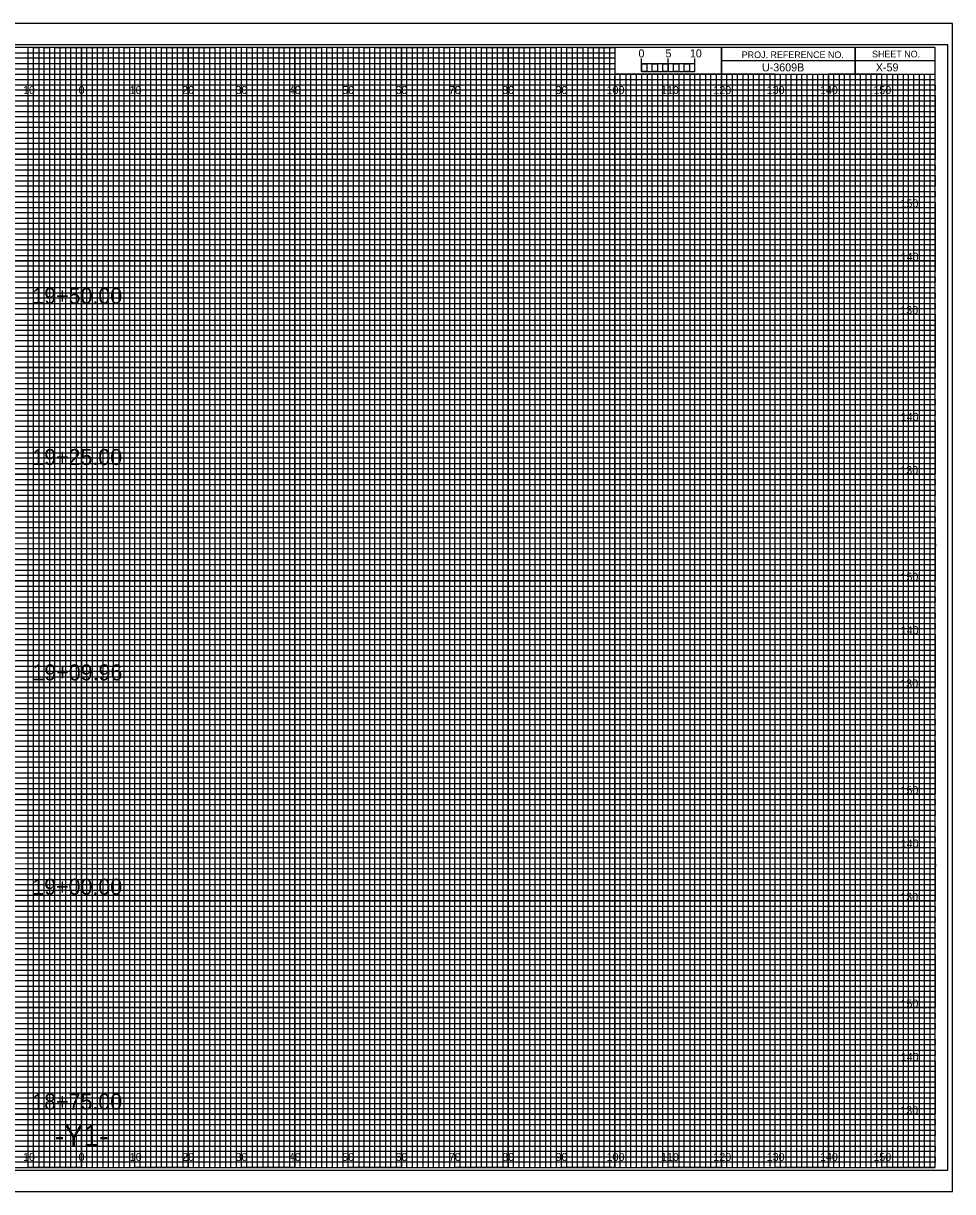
# Model space of a CAD drawing. Extents: x -13 to 323, y -5 to 2634.
# Drawn here: x 149.1 to 323.3, y 1535.5 to 1754.5 of the extents above; entities that cross this region are included whole.
import ezdxf

# ---------------------------------------------------------------- set-up
doc = ezdxf.new("R2010")
doc.units = 0
for name, color, linetype in [('Exist Cross Section Cell', 7, 'Continuous'), ('Exist XS Center Line Elevation Label', 7, 'Continuous'), ('Exist XS Ground Line', 7, 'Continuous'), ('Prop CMT Pvmt Course 1', 7, 'Continuous'), ('Prop CMT Pvmt Course 1 Wedge', 7, 'Continuous'), ('Prop CMT Pvmt Course 2', 7, 'Continuous'), ('Prop CMT Pvmt Course 2 Wedge', 7, 'Continuous'), ('Prop CMT Pvmt Course 3', 7, 'Continuous'), ('Prop CMT Pvmt Course 3 Wedge', 7, 'Continuous'), ('Prop CMT Pvmt Surface Shoulder', 7, 'Continuous'), ('Prop CMT Pvmt Wedge Surface 3', 7, 'Continuous'), ('Prop CMT Shld Paved Course 1', 7, 'Continuous'), ('Prop CMT Shld Paved Course 2', 7, 'Continuous'), ('Prop CMT Shld Paved Course 3', 7, 'Continuous'), ('Prop CMT Slope Grass', 7, 'Continuous'), ('Prop CMT Subgrade Earthwork', 7, 'Continuous'), ('Scratch_Level_0', 7, 'Continuous')]:
    doc.layers.add(name, color=color, linetype=linetype)

msp = doc.modelspace()

# ---------------------------------------------------------------- linework, layer by layer
at = {"layer": 'Exist XS Center Line Elevation Label'}
for points in [[(145, 1540), (155, 1540), (155, 1750), (165, 1750), (165, 1540), (175, 1540), (175, 1750), (185, 1750), (185, 1540), (195, 1540), (195, 1750), (205, 1750), (205, 1540), (215, 1540), (215, 1750), (225, 1750), (225, 1540), (235, 1540), (235, 1750), (245, 1750), (245, 1540), (255, 1540), (255, 1750), (259.93, 1750), (260, 1750), (260, 1745), (264.99, 1745), (264.99, 1540), (275, 1540), (275, 1745), (285, 1745), (285, 1540), (295, 1540), (295, 1745), (305, 1745), (305, 1540), (315, 1540), (315, 1745)], [(0, 1745), (275, 1745)], [(0, 1725), (320, 1725), (320, 1735), (0, 1735)], [(0, 1705), (320, 1705), (320, 1715), (0, 1715)], [(0, 1685), (320, 1685), (320, 1695), (0, 1695)], [(0, 1665), (320, 1665), (320, 1675), (0, 1675)], [(0, 1645), (320, 1645), (320, 1655), (0, 1655)], [(0, 1625), (320, 1625), (320, 1635), (0, 1635)], [(0, 1605), (320, 1605), (320, 1615), (0, 1615)], [(0, 1585), (320, 1585), (320, 1595), (0, 1595)], [(0, 1565), (320, 1565), (320, 1575), (0, 1575)], [(0, 1545), (320, 1545), (320, 1555), (0, 1555)]]:
    msp.add_lwpolyline(points, dxfattribs=at)
at = {"layer": 'Exist XS Ground Line'}
for p, q in [((150, 1750), (140, 1750)), ((150, 1540), (150, 1750)), ((170, 1750), (160, 1750)), ((160, 1750), (160, 1540)), ((170, 1540), (170, 1750)), ((190, 1750), (180, 1750)), ((180, 1750), (180, 1540)), ((190, 1540), (190, 1750)), ((210, 1750), (200, 1750)), ((200, 1750), (200, 1540)), ((210, 1540), (210, 1750)), ((230, 1750), (220, 1750)), ((220, 1750), (220, 1540)), ((230, 1540), (230, 1750)), ((250, 1750), (240, 1750)), ((240, 1750), (240, 1540)), ((250, 1540), (250, 1750)), ((260, 1750), (260, 1540)), ((270, 1540), (270, 1745)), ((290, 1745), (280, 1745)), ((280, 1745), (280, 1540)), ((290, 1540), (290, 1745)), ((310, 1745), (300, 1745)), ((300, 1745), (300, 1540)), ((310, 1540), (310, 1745)), ((160, 1540), (150, 1540)), ((180, 1540), (170, 1540)), ((200, 1540), (190, 1540)), ((220, 1540), (210, 1540)), ((240, 1540), (230, 1540)), ((260, 1540), (250, 1540)), ((280, 1540), (270, 1540)), ((300, 1540), (290, 1540)), ((320, 1540), (310, 1540)), ((320, 1540), (320, 1540))]:
    msp.add_line(p, q, dxfattribs=at)
for points in [[(0, 1740), (320, 1740), (320, 1730), (0, 1730)], [(0, 1720), (320, 1720), (320, 1710), (0, 1710)], [(0, 1700), (320, 1700), (320, 1690), (0, 1690)], [(0, 1680), (320, 1680), (320, 1670), (0, 1670)], [(0, 1660), (320, 1660), (320, 1650), (0, 1650)], [(0, 1640), (320, 1640), (320, 1630), (0, 1630)], [(0, 1620), (320, 1620), (320, 1610), (0, 1610)], [(0, 1600), (320, 1600), (320, 1590), (0, 1590)], [(0, 1580), (320, 1580), (320, 1570), (0, 1570)], [(0, 1560), (320, 1560), (320, 1550), (0, 1550)]]:
    msp.add_lwpolyline(points, dxfattribs=at)
at = {"layer": 'Prop CMT Pvmt Course 1'}
for p, q in [((265, 1745.49), (265, 1747.9)), ((265, 1746.9), (265, 1747.9)), ((270, 1745.49), (270, 1747.9)), ((275, 1745.49), (275, 1747.9)), ((275, 1746.9), (275, 1747.9))]:
    msp.add_line(p, q, dxfattribs=at)
for points in [[(275, 1746.9), (265, 1746.9), (265, 1745.49), (275, 1745.49)], [(265, 1746.9), (266, 1746.9), (266, 1745.49), (265, 1745.49)], [(267, 1746.9), (268, 1746.9), (268, 1745.49), (267, 1745.49)], [(269, 1746.9), (270, 1746.9), (270, 1745.49), (269, 1745.49)], [(271, 1746.9), (272, 1746.9), (272, 1745.49), (271, 1745.49)], [(273, 1746.9), (274, 1746.9), (274, 1745.49), (273, 1745.49)]]:
    msp.add_lwpolyline(points, close=True, dxfattribs=at)
at = {"layer": 'Prop CMT Pvmt Surface Shoulder'}
for p, q in [((267, 1745), (266.01, 1745)), ((266.01, 1745), (266.01, 1540)), ((267, 1540), (267, 1745)), ((269, 1745), (268, 1745)), ((268, 1745), (268, 1540)), ((269, 1540), (269, 1745)), ((266.01, 1540), (265, 1540)), ((268, 1540), (267, 1540))]:
    msp.add_line(p, q, dxfattribs=at)
for points in [[(150, 1540), (151, 1540), (151, 1750), (152, 1750), (152, 1540)], [(152, 1540), (153, 1540), (153, 1750), (154, 1750), (154, 1540)], [(155, 1540), (156, 1540), (156, 1750), (157, 1750), (157, 1540)], [(157, 1540), (158, 1540), (158, 1750), (159, 1750), (159, 1540)], [(160, 1540), (161, 1540), (161, 1750), (162, 1750), (162, 1540)], [(162, 1540), (163, 1540), (163, 1750), (164, 1750), (164, 1540)], [(165, 1540), (166, 1540), (166, 1750), (167, 1750), (167, 1540)], [(167, 1540), (168, 1540), (168, 1750), (169, 1750), (169, 1540)], [(170, 1540), (171, 1540), (171, 1750), (172, 1750), (172, 1540)], [(172, 1540), (173, 1540), (173, 1750), (174, 1750), (174, 1540)], [(175, 1540), (176, 1540), (176, 1750), (177, 1750), (177, 1540)], [(177, 1540), (178, 1540), (178, 1750), (179, 1750), (179, 1540)], [(180, 1540), (181, 1540), (181, 1750), (182, 1750), (182, 1540)], [(182, 1540), (183, 1540), (183, 1750), (184, 1750), (184, 1540)], [(185, 1540), (186, 1540), (186, 1750), (187, 1750), (187, 1540)], [(187, 1540), (188, 1540), (188, 1750), (189, 1750), (189, 1540)], [(190, 1540), (191, 1540), (191, 1750), (192, 1750), (192, 1540)], [(192, 1540), (193, 1540), (193, 1750), (194, 1750), (194, 1540)], [(195, 1540), (196, 1540), (196, 1750), (197, 1750), (197, 1540)], [(197, 1540), (198, 1540), (198, 1750), (199, 1750), (199, 1540)], [(200, 1540), (201, 1540), (201, 1750), (202, 1750), (202, 1540)], [(202, 1540), (203, 1540), (203, 1750), (204, 1750), (204, 1540)], [(205, 1540), (206, 1540), (206, 1750), (207, 1750), (207, 1540)], [(207, 1540), (208, 1540), (208, 1750), (209, 1750), (209, 1540)], [(210, 1540), (211, 1540), (211, 1750), (212, 1750), (212, 1540)], [(212, 1540), (213, 1540), (213, 1750), (214, 1750), (214, 1540)], [(215, 1540), (216, 1540), (216, 1750), (217, 1750), (217, 1540)], [(217, 1540), (218, 1540), (218, 1750), (219, 1750), (219, 1540)], [(220, 1540), (221, 1540), (221, 1750), (222, 1750), (222, 1540)], [(222, 1540), (223, 1540), (223, 1750), (224, 1750), (224, 1540)], [(225, 1540), (226, 1540), (226, 1750), (227, 1750), (227, 1540)], [(227, 1540), (228, 1540), (228, 1750), (229, 1750), (229, 1540)], [(230, 1540), (231, 1540), (231, 1750), (232, 1750), (232, 1540)], [(232, 1540), (233, 1540), (233, 1750), (234, 1750), (234, 1540)], [(235, 1540), (236, 1540), (236, 1750), (237, 1750), (237, 1540)], [(237, 1540), (238, 1540), (238, 1750), (239, 1750), (239, 1540)], [(240, 1540), (241, 1540), (241, 1750), (242, 1750), (242, 1540)], [(242, 1540), (243, 1540), (243, 1750), (244, 1750), (244, 1540)], [(245, 1540), (246, 1540), (246, 1750), (247, 1750), (247, 1540)], [(247, 1540), (248, 1540), (248, 1750), (249, 1750), (249, 1540)], [(250, 1540), (251, 1540), (251, 1750), (252, 1750), (252, 1540)], [(252, 1540), (253, 1540), (253, 1750), (254, 1750), (254, 1540)], [(255, 1540), (256, 1540), (256, 1750), (257, 1750), (257, 1540)], [(257, 1540), (258, 1540), (258, 1750), (259, 1750), (259, 1540)], [(260, 1540), (261, 1540), (261, 1745), (262.02, 1745), (262.02, 1540)], [(262, 1540), (263, 1540), (263, 1745), (263.99, 1745), (263.99, 1540)], [(270, 1540), (270.98, 1540), (270.98, 1745), (272, 1745), (272, 1540)], [(272, 1540), (273, 1540), (273, 1745), (274.05, 1745), (274.05, 1540)], [(275, 1540), (276, 1540), (276, 1745), (277, 1745), (277, 1540)], [(277, 1540), (278, 1540), (278, 1745), (279, 1745), (279, 1540)], [(280, 1540), (281, 1540), (281, 1745), (282, 1745), (282, 1540)], [(282, 1540), (283, 1540), (283, 1745), (284, 1745), (284, 1540)], [(285, 1540), (286, 1540), (286, 1745), (287, 1745), (287, 1540)], [(287, 1540), (288, 1540), (288, 1745), (289, 1745), (289, 1540)], [(290, 1540), (291, 1540), (291, 1745), (292, 1745), (292, 1540)], [(292, 1540), (293, 1540), (293, 1745), (294, 1745), (294, 1540)], [(295, 1540), (296, 1540), (296, 1745), (297, 1745), (297, 1540)], [(297, 1540), (298, 1540), (298, 1745), (299, 1745), (299, 1540)], [(300, 1540), (301, 1540), (301, 1745), (302, 1745), (302, 1540)], [(302, 1540), (303, 1540), (303, 1745), (304, 1745), (304, 1540)], [(305, 1540), (306, 1540), (306, 1745), (307, 1745), (307, 1540)], [(307, 1540), (308, 1540), (308, 1745), (309, 1745), (309, 1540)], [(310, 1540), (311, 1540), (311, 1745), (312, 1745), (312, 1540)], [(312, 1540), (313, 1540), (313, 1745), (314, 1745), (314, 1540)], [(315, 1540), (316, 1540), (316, 1745), (317, 1745), (317, 1540)], [(317, 1540), (318, 1540), (318, 1745), (319, 1745), (319, 1540)]]:
    msp.add_lwpolyline(points, dxfattribs=at)
at = {"layer": 'Prop CMT Pvmt Wedge Surface 3'}
for p, q in [((305, 1750), (305, 1745)), ((305, 1745), (305, 1750)), ((280, 1747.5), (280, 1745)), ((320, 1747.49), (280, 1747.49)), ((280, 1745), (320, 1745))]:
    msp.add_line(p, q, dxfattribs=at)
for points in [[(320, 1750), (0, 1750), (0, 1540), (320, 1540)], [(280, 1750), (260, 1750), (260, 1745.03), (280, 1745.03)], [(320, 1750), (280, 1750), (280, 1745), (320, 1745)]]:
    msp.add_lwpolyline(points, close=True, dxfattribs=at)
at = {"layer": 'Prop CMT Shld Paved Course 1'}
for p, q in [((150, 1540), (150, 1750)), ((160, 1540), (160, 1750)), ((170, 1540), (170, 1750)), ((180, 1540), (180, 1750)), ((190, 1540), (190, 1750)), ((200, 1540), (200, 1750)), ((210, 1540), (210, 1750)), ((220, 1540), (220, 1750)), ((230, 1540), (230, 1750)), ((240, 1540), (240, 1750)), ((250, 1540), (250, 1750)), ((260, 1540), (260, 1744.69)), ((270, 1540), (270, 1744.69)), ((280, 1540), (280, 1744.69)), ((290, 1540), (290, 1744.69)), ((300, 1540), (300, 1744.69)), ((310, 1540), (310, 1744.69)), ((0, 1740), (320, 1740)), ((0, 1730), (320, 1730)), ((0, 1720), (320, 1720)), ((0, 1710), (320, 1710)), ((0, 1700), (320, 1700)), ((0, 1690), (320, 1690)), ((0, 1680), (320, 1680)), ((0, 1670), (320, 1670)), ((0, 1660), (320, 1660)), ((0, 1650), (320, 1650)), ((0, 1640), (320, 1640)), ((0, 1630), (320, 1630)), ((0, 1620), (320, 1620)), ((0, 1610), (320, 1610)), ((0, 1600), (320, 1600)), ((0, 1590), (320, 1590)), ((0, 1580), (320, 1580)), ((0, 1570), (320, 1570)), ((0, 1560), (320, 1560)), ((0, 1550), (320, 1550))]:
    msp.add_line(p, q, dxfattribs=at)
at = {"layer": 'Prop CMT Shld Paved Course 2'}
for p, q in [((323.3, 1754.5), (-13.4, 1754.5)), ((-13.4, 1535.5), (323.3, 1535.5))]:
    msp.add_line(p, q, dxfattribs=at)
at = {"layer": 'Prop CMT Slope Grass'}
msp.add_lwpolyline([(-10.8, 1539.5), (322.4, 1539.5), (322.4, 1750.5), (-10.8, 1750.5)], close=True, dxfattribs=at)
at = {"layer": 'Prop CMT Subgrade Earthwork'}
msp.add_lwpolyline([(-13.4, 1535.5), (323.3, 1535.5), (323.3, 1754.5), (-13.4, 1754.5)], close=True, dxfattribs=at)
at = {"layer": 'Scratch_Level_0'}
for p, q in [((0, 1749), (260, 1749)), ((260, 1747.98), (0, 1747.98)), ((260, 1749), (260, 1747.98)), ((0, 1747), (260, 1747)), ((260, 1745.89), (0, 1745.89)), ((260, 1747), (260, 1745.89)), ((0, 1744), (320, 1744))]:
    msp.add_line(p, q, dxfattribs=at)
for points in [[(0, 1743), (270, 1743), (320, 1743), (320, 1742), (0, 1742)], [(0, 1741), (320, 1741), (320, 1739), (0, 1739)], [(0, 1738), (320, 1738), (320, 1737), (0, 1736.98)], [(0, 1736), (320, 1736), (320, 1734), (0, 1734)], [(0, 1733), (320, 1733), (320, 1732), (0, 1732)], [(0, 1731), (320, 1731), (320, 1729), (0, 1729)], [(0, 1728), (320, 1728), (320, 1727), (0, 1727)], [(0, 1726), (320, 1726), (320, 1724), (0, 1724)], [(0, 1723), (320, 1723), (320, 1722), (0, 1722)], [(0, 1721), (320, 1721), (320, 1719), (0, 1719)], [(0, 1718), (320, 1718), (320, 1717), (0, 1717)], [(0, 1716), (320, 1716), (320, 1713.95), (320, 1713), (320, 1712), (0, 1712)], [(0, 1714), (320, 1714), (320, 1713), (0, 1713)], [(0, 1711), (320, 1711), (320, 1709), (0, 1709.03)], [(0, 1709.03), (320, 1709), (320, 1708), (0, 1708)], [(0, 1707), (320, 1707), (320, 1706), (0, 1706)], [(0, 1704), (320, 1704), (320, 1703), (0, 1703)], [(0, 1702), (320, 1702), (320, 1701), (0, 1701)], [(-0.07, 1698.89), (320, 1698.89), (320, 1697.88), (-0.07, 1697.88)], [(0, 1697), (320, 1697), (320, 1696), (0, 1696)], [(0, 1694), (320, 1694), (320, 1693), (0, 1693)], [(0, 1692), (320, 1692), (320, 1691), (0, 1691)], [(0, 1689), (320, 1689), (320, 1688), (0, 1688)], [(0, 1687), (320, 1687), (320, 1686), (0, 1686)], [(0, 1684), (320, 1684), (320, 1683), (0, 1683)], [(0, 1682), (320, 1682), (320, 1681), (0, 1681)], [(0, 1679), (320, 1679), (319.99, 1677.98), (0, 1678)], [(0, 1677), (320, 1677), (320, 1676), (0, 1676)], [(0, 1674), (320, 1674), (320, 1673), (0, 1673)], [(0, 1672), (320, 1672), (320, 1671), (0, 1671)], [(0, 1669), (320, 1669), (320, 1668), (0, 1668)], [(0, 1667), (320, 1667), (320, 1666), (0, 1666)], [(0, 1664), (320, 1664), (320, 1663), (0, 1663)], [(0, 1662), (320, 1662), (320, 1661), (0, 1661)], [(0, 1659), (320, 1659), (320, 1658), (0, 1658)], [(0, 1656.99), (320.07, 1656.91), (320, 1656), (0, 1656)], [(0, 1654), (320, 1654), (320, 1653), (0, 1653)], [(0, 1652), (320, 1652), (320, 1651), (0, 1651)], [(0, 1649), (320, 1649), (320, 1648), (0, 1648)], [(0, 1647), (320, 1647), (320, 1646), (0, 1646)], [(0, 1644), (320, 1644), (320, 1643), (0, 1643)], [(0, 1642), (320, 1642), (320, 1641), (0, 1641)], [(0, 1639), (320, 1639), (320, 1638), (0, 1638)], [(0, 1637), (320, 1637), (320, 1636), (0, 1636)], [(0, 1634), (320, 1634), (320, 1633), (0, 1633)], [(0, 1632), (320, 1632), (320, 1631), (0, 1631)], [(0, 1629), (320, 1629), (320, 1628), (0, 1628)], [(0, 1627), (320, 1627), (320, 1626), (0, 1626)], [(0, 1624), (320, 1624), (320, 1623), (0, 1623)], [(0, 1622), (320, 1622), (320, 1621), (0, 1621)], [(0, 1619), (320, 1619), (319.99, 1617.98), (0, 1618)], [(0, 1617), (320, 1617), (320, 1616), (0, 1616)], [(0, 1614), (320, 1614), (320, 1613), (0, 1613)], [(0, 1612), (320, 1612), (320, 1611), (0, 1611)], [(0, 1609), (320, 1609), (320, 1608), (0, 1608)], [(0, 1607), (320, 1607), (320, 1606), (0, 1606)], [(0, 1604), (320, 1604), (320, 1603), (0, 1603)], [(0, 1602), (320, 1602), (320, 1601), (0, 1601)], [(0, 1599), (320, 1599), (320, 1598), (0, 1598)], [(0, 1596.99), (320.07, 1596.91), (320, 1596), (0, 1596)], [(0, 1594), (320, 1594), (320, 1593), (0, 1593)], [(0, 1592), (320, 1592), (320, 1591), (0, 1591)], [(0, 1589), (320, 1589), (320, 1588), (0, 1588)], [(0, 1587), (320, 1587), (320, 1586), (0, 1586)], [(0, 1584), (320, 1584), (320, 1583), (0, 1583)], [(0, 1582), (320, 1582), (320, 1581), (0, 1581)], [(0, 1579), (320, 1579), (320, 1578), (0, 1578)], [(0, 1577), (320, 1577), (320, 1576), (0, 1576)], [(0, 1574), (320, 1574), (320, 1573), (0, 1573)], [(0, 1572), (320, 1572), (320, 1571), (0, 1571)], [(0, 1569), (320, 1569), (320, 1568), (0, 1568)], [(0, 1567), (320, 1567), (320, 1566), (0, 1566)], [(0, 1564), (320, 1564), (320, 1563), (0, 1563)], [(0, 1562), (320, 1562), (320, 1561), (0, 1561)], [(0, 1559), (320, 1559), (320, 1558), (0, 1558)], [(0, 1557), (320, 1557), (320, 1556), (0, 1556)], [(0, 1554), (320, 1554), (320, 1553), (0, 1553)], [(0, 1552), (320, 1552), (320, 1551), (0, 1551)], [(0, 1549), (320, 1549), (320, 1548), (0, 1548)], [(0, 1547), (320, 1547), (320, 1546), (0, 1546)], [(0, 1544), (320, 1544), (320, 1543), (0, 1543)], [(0, 1542), (320, 1542), (320, 1541), (0, 1541)]]:
    msp.add_lwpolyline(points, dxfattribs=at)

# ---------------------------------------------------------------- texts
at = {"layer": 'Exist Cross Section Cell'}
for s, p in [('10', (149.04, 1741.25)), ('0', (159.45, 1741.25)), ('0', (159.45, 1741.25)), ('10', (169.04, 1741.25)), ('20', (178.86, 1741.25)), ('30', (188.86, 1741.25)), ('40', (198.86, 1741.25)), ('50', (208.86, 1741.25)), ('60', (218.86, 1741.25)), ('70', (228.86, 1741.25)), ('80', (238.86, 1741.25)), ('90', (248.86, 1741.25)), ('100', (258.44, 1741.25)), ('110', (268.62, 1741.25)), ('120', (278.44, 1741.25)), ('130', (288.44, 1741.25)), ('140', (298.44, 1741.25)), ('150', (308.44, 1741.25)), ('10', (149.04, 1541.25)), ('0', (159.45, 1541.25)), ('0', (159.45, 1541.25)), ('10', (169.04, 1541.25)), ('20', (178.86, 1541.25)), ('30', (188.86, 1541.25)), ('40', (198.86, 1541.25)), ('50', (208.86, 1541.25)), ('60', (218.86, 1541.25)), ('70', (228.86, 1541.25)), ('80', (238.86, 1541.25)), ('90', (248.86, 1541.25)), ('100', (258.44, 1541.25)), ('110', (268.62, 1541.25)), ('120', (278.44, 1541.25)), ('130', (288.44, 1541.25)), ('140', (298.44, 1541.25)), ('150', (308.44, 1541.25))]:
    msp.add_text(s, height=1.5, dxfattribs=at).set_placement(p)
at = {"layer": 'Prop CMT Pvmt Course 1'}
msp.add_text('0', height=1.5, dxfattribs=at).set_placement((264.41, 1748.12))
at = {"layer": 'Prop CMT Pvmt Course 1 Wedge'}
msp.add_text('U-3609B', height=1.5, dxfattribs=at).set_placement((287.56, 1745.5))
at = {"layer": 'Prop CMT Pvmt Course 2'}
for s, p in [('19+50.00', (150.77, 1701.93)), ('19+25.00', (150.77, 1671.71)), ('19+09.96', (150.8, 1631.34)), ('19+00.00', (150.77, 1591.16)), ('18+75.00', (150.77, 1550.88))]:
    msp.add_text(s, height=3, dxfattribs=at).set_placement(p)
at = {"layer": 'Prop CMT Pvmt Course 2 Wedge'}
msp.add_text('-Y1-', height=4, dxfattribs=at).set_placement((154.99, 1544))
at = {"layer": 'Prop CMT Pvmt Course 3'}
msp.add_text('X-59', height=1.5, dxfattribs=at).set_placement((308.9, 1745.5))
at = {"layer": 'Prop CMT Pvmt Course 3 Wedge'}
for s, p in [('5', (269.47, 1748.12)), ('10', (274.04, 1748.12))]:
    msp.add_text(s, height=1.5, dxfattribs=at).set_placement(p)
at = {"layer": 'Prop CMT Pvmt Wedge Surface 3'}
for s, p in [('PROJ. REFERENCE NO.', (283.77, 1747.99)), ('SHEET NO.', (308.19, 1748.12))]:
    msp.add_text(s, height=1.25, dxfattribs=at).set_placement(p)
at = {"layer": 'Prop CMT Shld Paved Course 3'}
for s, p in [('150', (313.52, 1720)), ('140', (313.57, 1710)), ('130', (313.49, 1700)), ('140', (313.57, 1680)), ('130', (313.49, 1670)), ('150', (313.52, 1650)), ('140', (313.57, 1640)), ('130', (313.49, 1630)), ('150', (313.52, 1610)), ('140', (313.57, 1600)), ('130', (313.49, 1590)), ('150', (313.52, 1570)), ('140', (313.57, 1560)), ('130', (313.49, 1550))]:
    msp.add_text(s, height=1.5, dxfattribs=at).set_placement(p)

doc.saveas('drawing.dxf')
